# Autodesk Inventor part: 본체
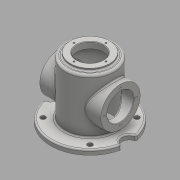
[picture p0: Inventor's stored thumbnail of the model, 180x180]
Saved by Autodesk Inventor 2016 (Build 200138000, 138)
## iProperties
Created: 2018-04
Part Number: 본체
Material: 일반
Document SubType Name: Modeling
Designer: 605-17
Density: 1 g/cm^3
Appearance: 기본값
Author: 605-17
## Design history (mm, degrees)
sketch "스케치1"
  geometry: C1 r 50 at (0, 0); 1 further point
  constraints: 1 centre point, 1 coincident
  dimensions: "d0" = 100 diameter of C1
extrude "돌출1" new body sketch "스케치1" distance "d1" = 128; taper "d2" = 0 deg
sketch "스케치2"
  geometry: C1 r 40 at (0, 0); 1 further point
  constraints: 1 centre point, 1 coincident
  dimensions: "d3" = 80 diameter of C1
extrude "돌출2" join sketch "스케치2" distance "d4" = 5; taper "d5" = 0 deg
node "작업 평면1"
sketch "스케치3"
  geometry: C1 r 80 at (0, 0); 1 further point
  constraints: 1 centre point, 1 coincident
  dimensions: "d7" = 160 diameter of C1
extrude "돌출3" join sketch "스케치3" distance "d8" = 10; taper "d9" = 0 deg
sketch "스케치6"
  geometry: L1 (-80, 8)-(80, 8) reference; C1 r 40 at (0, 68); 1 further point
  constraints: 1 centre point
  dimensions: "d16" = 80 diameter of C1; "d17" = 60 distance from line of C1.centre L1
extrude "돌출6" join sketch "스케치6" stored distance "d18" = 124; taper "d19" = 0 deg
sketch "스케치4"
  geometry: C1 r 27 at (0, 0); 1 further point
  constraints: 1 centre point, 1 coincident
  dimensions: "d10" = 54 diameter of C1
extrude "돌출4" cut sketch "스케치4" distance "d11" = 13; taper "d12" = 0 deg
sketch "스케치5"
  geometry: C1 r 45 at (0, 0); 1 further point
  constraints: 1 centre point, 1 coincident
  dimensions: "d13" = 90 diameter of C1
extrude "돌출5" cut sketch "스케치5" distance "d14" = 120; taper "d15" = 0 deg
sketch "스케치7"
  geometry: C1 r 27 at (0, 0); 1 further point
  constraints: 1 centre point
  dimensions: "d20" = 54 diameter of C1
extrude "돌출7" cut sketch "스케치7" stored distance "d21" = 124; taper "d22" = 0 deg
sketch "스케치8"
  geometry: L1 (0, 0)-(32.5, 0); 2 further points
  constraints: 2 end point, 1 coincident, 1 horizontal
  dimensions: "d23" = 32.5 distance of L1.start L1.end
hole "구멍1" sketch "스케치8" at (0, 0), (32.5, 0) diameter "d24" = 3.242; stored, may be unused: countersink angle "d28" = 90 deg, drill point angle "d30" = 118 deg; dims "d25" = 8, "d26" = 4, "d27" = 2, "d29" = 10
sketch "스케치9"
  geometry: L1 (0, 0)-(0, -32.5); C1 r 45 at (0, 0) reference; 2 further points
  constraints: 2 end point, 1 coincident, 1 vertical
  dimensions: "d34" = 32.5 distance of L1.start L1.end
hole "구멍2" sketch "스케치9" at (0, -32.5) diameter "d35" = 3.242; stored, may be unused: countersink angle "d39" = 90 deg, drill point angle "d41" = 118 deg; dims "d36" = 8, "d37" = 4, "d38" = 2, "d40" = 10
sketch "스케치10"
  geometry: C1 r 15 at (-80, 0); 2 further points
  constraints: 1 centre point, 1 horizontal alignment, 1 other
  dimensions: "d45" = 30 diameter of C1
extrude "돌출8" cut sketch "스케치10" distance "d46" = 10; taper "d47" = 0 deg
sketch "스케치11"
  geometry: L1 (0, 0)-(67.5, 0); C1 r 5 at (47.73, -47.73)
  constraints: 2 end point, 1 centre point, 1 horizontal
  dimensions: "d50" = 10 diameter of C1
extrude "돌출9" cut sketch "스케치11" distance "d51" = 10; taper "d52" = 0 deg
chamfer "모따기1" distance "d56" = 1; stored, may be unused: second distance "d57" = 2, angle "d58" = 45 deg
fillet "모깎기1" dims "d59" = 3
fillet "모깎기2" dims "d60" = 3
node "작업 평면2"
sketch "스케치12"
  geometry: L1 (-14.195, 38.156)-(-14.195, 117.844); L2 (-14.195, 117.844)-(13.853, 117.844); L3 (13.853, 117.844)-(13.853, 38.156); L4 (13.853, 38.156)-(-14.195, 38.156); L5 (-0.171, 38.156)-(-0.171, 117.844); L6 (-14.195, 78)-(13.853, 78); L7 (-77.955, 8)-(77.955, 8) reference; 2 further points
  constraints: 5 midpoint, 4 end point, 2 other
  dimensions: "d62" = 70 distance from line of L7 point (-0.171, 78)
feature "엠보싱1" sketch "스케치12" dims "d63" = 0.5, "d64" = 0
fillet "모깎기3" dims "d65" = 5
node "솔리드1"
pattern_circular "원형 패턴1" dims angle "d32" = 360 deg
mirror "대칭1"
pattern_circular "원형 패턴2" dims angle "d43" = 360 deg
mirror "대칭2"
pattern_circular "원형 패턴3" dims angle "d54" = 360 deg
other parameters: "d6" = 8, "d61" = 113.25
